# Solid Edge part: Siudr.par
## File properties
Author: Türk
Template: Iso Part.par
Last saved by: Türk
Revision: 3
Application: Solid Edge
Accuracy: 0,990
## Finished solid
Body 1: solid body, 24 faces, 60 edges, 38 vertices.
  Faces by surface: plane 17, cylinder 6, cone 1
  Edges by curve: line 35, circle 15, ellipse 8, intersection 2
Bounding box of the edges (mm): 45.000 x 60.000 x 192.587, from (-22.5, -30, -22.5) to (22.5, 30, 170.0869).
Cylindrical faces by radius (mm): R10 x5, R22.5 x1
Conical faces (half-angle, radius in mm at the cone's reference point): 45 deg R47.5 x1
Planar faces by outward normal: +x 1, +y 3, +z 1, -x 1, -y 3, oblique 8
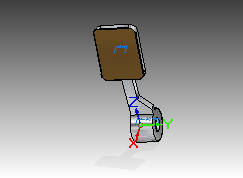
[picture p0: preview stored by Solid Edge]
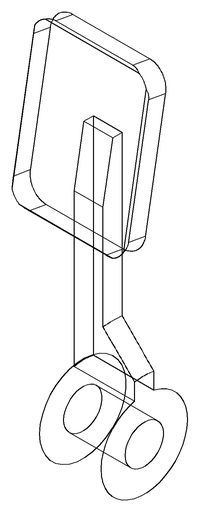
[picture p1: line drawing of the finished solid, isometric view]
